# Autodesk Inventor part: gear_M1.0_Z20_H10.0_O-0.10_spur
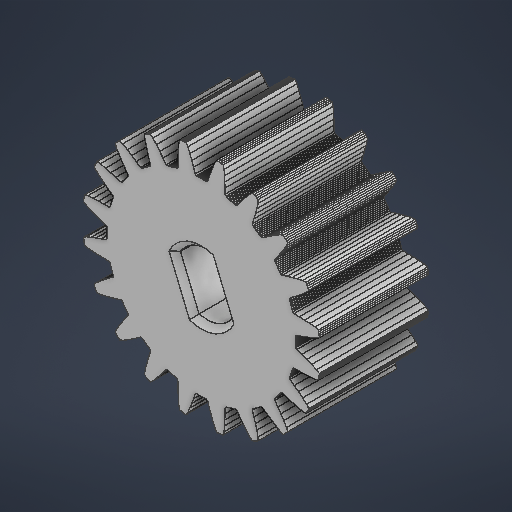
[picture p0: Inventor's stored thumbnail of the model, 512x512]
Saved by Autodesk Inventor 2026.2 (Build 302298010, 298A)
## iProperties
Company: Open CASCADE
Created: 2026-05
Part Number: gear_M1.0_Z20_H10.0_O-0.10_spur
Material: 일반
Description: Open CASCADE Model
Document SubType Name: Modeling
Designer: work
Authority: Unknown
Density: 1 g/cm^3
Appearance: 기본값
Sending System: Open CASCADE 7.8
Preprocessor: Open CASCADE STEP processor 7.8
Title: Open CASCADE Shape Model
Author: Author
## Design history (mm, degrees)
feature "기준1"
sketch "스케치1"
  geometry: C1 r 2.8 at (-9.73, 2.891); 1 further point
  constraints: 1 centre point, 1 coincident
  dimensions: "d0" = 5.6 diameter of C1
extrude "돌출1" cut sketch "스케치1" extent not by distance; stored distance "d1" = 0; taper "d2" = 0 deg
sketch "스케치2"
  geometry: L1 (-1.741, -0.426)-(-1.698, -0.321) reference; L2 (-1.698, -0.321)-(-1.657, -0.216) reference; L3 (-1.657, -0.216)-(-1.617, -0.11) reference; L4 (-1.617, -0.11)-(-1.578, -0.003) reference; L5 (-1.578, -0.003)-(-1.452, 0.073) reference; L6 (-1.452, 0.073)-(-0.97, 0.037) reference; L7 (-0.97, 0.037)-(-0.486, 0.012) reference; L8 (-0.486, 0.012)-(0, 0) reference; L9 (0, 0)-(0.488, 0) reference; L10 (0.488, 0)-(0.797, 0.061) reference; L11 (0.797, 0.061)-(0.833, 0.199) reference; L12 (0.833, 0.199)-(0.867, 0.337) reference; L13 (0.867, 0.337)-(0.9, 0.476) reference; L14 (0.9, 0.476)-(0.93, 0.616) reference; L15 (0.93, 0.616)-(0.683, 0.811) reference; L16 (0.683, 0.811)-(0.249, 1.033) reference; L17 (0.249, 1.033)-(-0.19, 1.243) reference; L18 (-0.19, 1.243)-(-0.632, 1.442) reference; L19 (-0.632, 1.442)-(-1.077, 1.629) reference; L20 (-1.077, 1.629)-(-1.155, 1.755) reference; L21 (-1.155, 1.755)-(-1.14, 1.867) reference; L22 (-1.14, 1.867)-(-1.128, 1.98) reference; L23 (-1.128, 1.98)-(-1.117, 2.092) reference; L24 (-1.117, 2.092)-(-1.107, 2.205) reference; L25 (-1.107, 2.205)-(-1.099, 2.318) reference; L26 (-1.099, 2.318)-(-1.092, 2.431) reference; L27 (-1.092, 2.431)-(-1.087, 2.544) reference; L28 (-1.087, 2.544)-(-1.083, 2.657) reference; L29 (-1.083, 2.657)-(-0.987, 2.769) reference; L30 (-0.987, 2.769)-(-0.517, 2.883) reference; L31 (-0.517, 2.883)-(-0.049, 3.01) reference; L32 (-0.049, 3.01)-(0.417, 3.148) reference; L33 (0.417, 3.148)-(0.881, 3.299) reference; L34 (0.881, 3.299)-(1.156, 3.452) reference; L35 (1.156, 3.452)-(1.148, 3.595) reference; L36 (1.148, 3.595)-(1.137, 3.737) reference; L37 (1.137, 3.737)-(1.125, 3.879) reference; L38 (1.125, 3.879)-(1.112, 4.021) reference; L39 (1.112, 4.021)-(0.816, 4.13) reference; L40 (0.816, 4.13)-(0.335, 4.207) reference; L41 (0.335, 4.207)-(-0.147, 4.272) reference; L42 (-0.147, 4.272)-(-0.629, 4.324) reference; L43 (-0.629, 4.324)-(-1.111, 4.364) reference; L44 (-1.111, 4.364)-(-1.223, 4.46) reference; L45 (-1.223, 4.46)-(-1.245, 4.571) reference; L46 (-1.245, 4.571)-(-1.267, 4.682) reference; L47 (-1.267, 4.682)-(-1.291, 4.793) reference; L48 (-1.291, 4.793)-(-1.317, 4.903) reference; L49 (-1.317, 4.903)-(-1.344, 5.013) reference; L50 (-1.344, 5.013)-(-1.373, 5.123) reference; L51 (-1.373, 5.123)-(-1.403, 5.232) reference; L52 (-1.403, 5.232)-(-1.434, 5.341) reference; L53 (-1.434, 5.341)-(-1.377, 5.477) reference; L54 (-1.377, 5.477)-(-0.966, 5.73) reference; L55 (-0.966, 5.73)-(-0.56, 5.995) reference; L56 (-0.56, 5.995)-(-0.159, 6.271) reference; L57 (-0.159, 6.271)-(0.236, 6.558) reference; L58 (0.236, 6.558)-(0.45, 6.789) reference; L59 (0.45, 6.789)-(0.398, 6.922) reference; L60 (0.398, 6.922)-(0.344, 7.054) reference; L61 (0.344, 7.054)-(0.289, 7.185) reference; L62 (0.289, 7.185)-(0.232, 7.316) reference; L63 (0.232, 7.316)-(-0.083, 7.328) reference; L64 (-0.083, 7.328)-(-0.565, 7.253) reference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; A1 r 2.8 centre (-9.73, 2.891) between (-9.73, 5.691) and (-11.43, 5.116) reference; 3 further points
  constraints: 6 end point, 3 point on circle, 2 symmetric about line, 2 vertical, 1 midpoint, 1 parallel
  dimensions: "d3" = 3.4 distance between parallel lines of L483 L482
extrude "돌출2" join sketch "스케치2" distance "d4" = 5.8; taper "d5" = 0 deg
chamfer "모따기1" distance "d6" = 2; stored, may be unused: second distance "d7" = 2, angle "d8" = 45 deg
sketch "스케치3"
  geometry: L1 (0.693, 20)-(-10.807, 8.5); L2 (-10.807, 8.5)-(-10.807, 20); L3 (-10.807, 20)-(0.693, 20); L4 (-10.807, 8.5)-(-10.807, 1.5); L5 (-10.807, 1.5)-(0.693, -10); L6 (-10.807, 1.5)-(-10.807, -10); L7 (-10.807, -10)-(0.693, -10); L8 (-10.807, 5)-(0, 5); L9 (0, 0)-(0, 10) reference; L10 (-10.807, 0)-(-10.807, 10) reference; L11 (0, 10)-(0, 0); L12 (-10.717, 0)-(-10.717, 10) reference; 1 further point
  constraints: 18 end point, 4 midpoint, 3 perpendicular, 2 collinear, 1 point on line, 1 vertical
  dimensions: "d9" = 45 deg angle of L6 L5; "d10" = 45 deg angle of L2 L1; "d11" = 7 distance of L4.end L1.end; "d12" = 30 distance between parallel lines of L7 L3; "d13" = 15 distance from line of L7 point (-10.717, 5)
chamfer "모따기2" distance "d14" = 0.5; stored, may be unused: second distance "d15" = 2, angle "d16" = 45 deg
node "솔리드1"
node "투영된 루프1"
